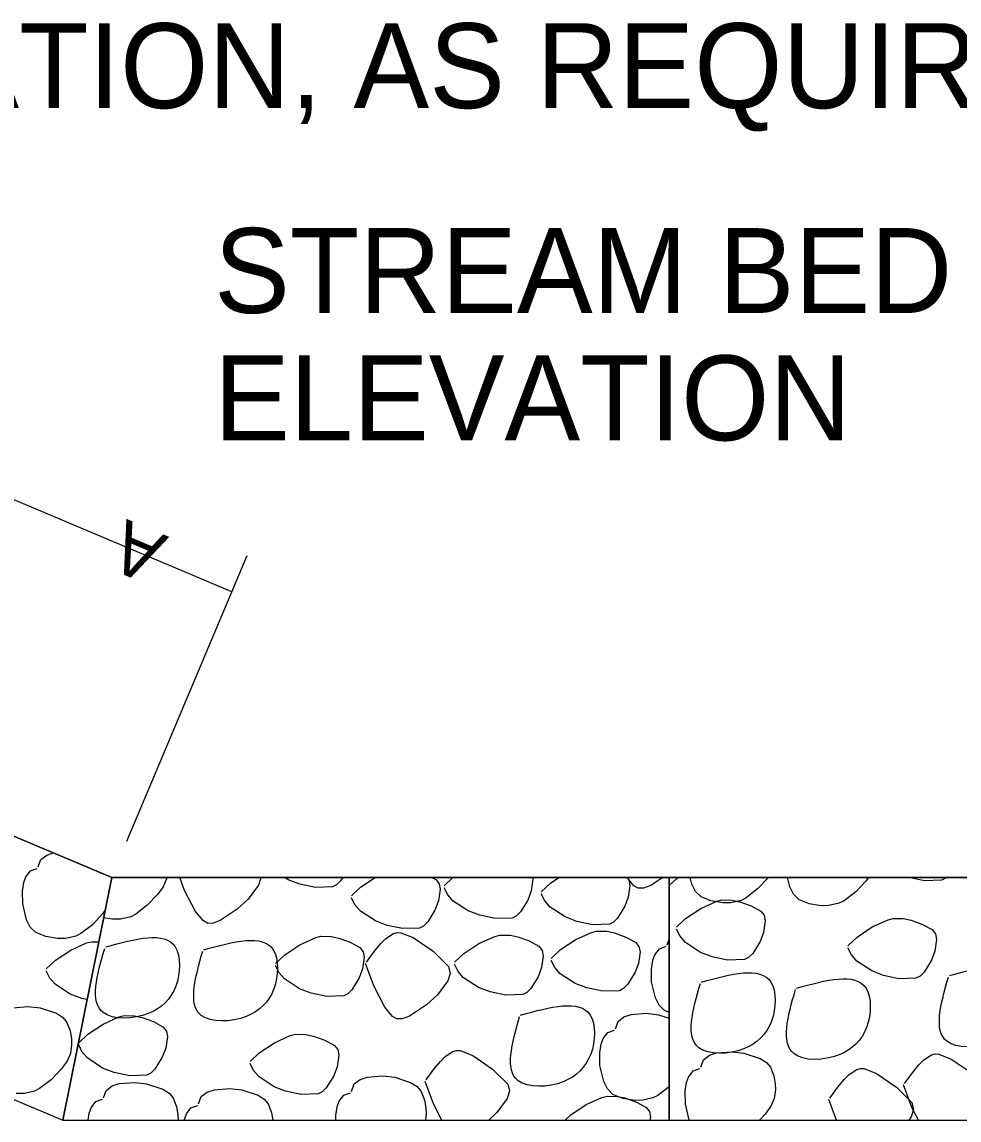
# Model space of a CAD drawing. Extents: x 3 to 3592, y -602 to 1171.
# Drawn here: x 2823.27 to 2861.89, y -276.9 to -231.64 of the extents above; entities that cross this region are included whole.
import ezdxf

# ---------------------------------------------------------------- set-up
doc = ezdxf.new("R2010")
doc.units = 0
doc.layers.add('2', color=7, linetype='Continuous')
doc.layers.add('3', color=7, linetype='Continuous')

msp = doc.modelspace()

# ---------------------------------------------------------------- linework, layer by layer
at = {"layer": '2'}
for p, q in [((2831.922, -255.129), (2816.821, -248.771)), ((2827.596, -265.403), (2832.553, -253.631)), ((2826.966, -266.901), (2824.946, -276.901)), ((2849.946, -276.901), (2849.946, -266.901))]:
    msp.add_line(p, q, dxfattribs=at)
for points in [[(2764.046, -240.408), (2826.966, -266.901), (2872.927, -266.901), (2935.846, -240.408)], [(2777.446, -256.901), (2824.946, -276.901), (2874.946, -276.901), (2922.446, -256.901)], [(2824.046, -266.166), (2824.288, -265.984)], [(2824.288, -265.984), (2824.566, -265.89)], [(2823.619, -266.629), (2823.896, -266.531)], [(2823.936, -266.471), (2824.046, -266.166)], [(2823.346, -267.108), (2823.429, -266.879)], [(2823.429, -266.879), (2823.619, -266.629)], [(2826.956, -266.897), (2826.961, -266.924)], [(2829.227, -266.966), (2829.09, -267.284)], [(2829.237, -266.901), (2829.227, -266.966)], [(2829.973, -267.436), (2829.775, -266.901)], [(2833.117, -266.919), (2833.021, -267.221)], [(2833.113, -266.901), (2833.117, -266.919)], [(2834.246, -266.996), (2834.1, -266.901)], [(2834.724, -267.179), (2834.246, -266.996)], [(2836.487, -266.901), (2836.4, -267.041)], [(2837.225, -267.298), (2837.824, -266.901)], [(2840.156, -266.901), (2840.323, -266.991)], [(2840.323, -266.991), (2840.463, -267.168)], [(2840.673, -267.244), (2841.031, -266.901)], [(2844.33, -266.978), (2844.26, -267.458)], [(2844.315, -266.901), (2844.33, -266.978)], [(2845.049, -267.135), (2845.403, -266.901)], [(2848.204, -266.901), (2848.287, -267.006)], [(2848.496, -267.243), (2848.213, -266.901)], [(2848.287, -267.006), (2848.33, -267.229)], [(2849.69, -266.901), (2849.191, -267.229)], [(2850.235, -266.969), (2849.946, -267.235)], [(2850.286, -266.901), (2850.235, -266.969)], [(2850.878, -267.177), (2850.813, -266.901)], [(2854.011, -266.934), (2853.592, -267.375)], [(2854.036, -266.901), (2854.011, -266.934)], [(2854.92, -267.295), (2854.828, -266.901)], [(2858.164, -266.901), (2858.053, -267.052)], [(2859.829, -266.902), (2859.825, -266.901)], [(2860.47, -267.037), (2859.829, -266.902)], [(2861.337, -266.929), (2861.171, -267.016)], [(2861.366, -266.901), (2861.337, -266.929)], [(2823.289, -267.466), (2823.346, -267.108)], [(2829.09, -267.284), (2828.854, -267.607)], [(2830.427, -268.304), (2829.973, -267.436)], [(2833.021, -267.221), (2832.593, -267.8)], [(2835.365, -267.314), (2834.724, -267.179)], [(2836.066, -267.293), (2835.365, -267.314)], [(2836.232, -267.206), (2836.066, -267.293)], [(2836.4, -267.041), (2836.232, -267.206)], [(2836.849, -267.657), (2837.225, -267.298)], [(2840.506, -267.392), (2840.437, -267.872)], [(2840.463, -267.168), (2840.506, -267.392)], [(2840.818, -267.619), (2840.673, -267.325)], [(2844.26, -267.458), (2844.117, -267.837)], [(2844.673, -267.495), (2845.049, -267.135)], [(2848.33, -267.229), (2848.261, -267.709)], [(2848.673, -267.348), (2848.496, -267.243)], [(2848.893, -267.342), (2848.673, -267.348)], [(2849.191, -267.229), (2848.893, -267.342)], [(2851.031, -267.478), (2850.878, -267.177)], [(2853.592, -267.375), (2853.116, -267.742)], [(2855.073, -267.596), (2854.92, -267.295)], [(2858.053, -267.052), (2857.634, -267.493)], [(2861.171, -267.016), (2860.47, -267.037)], [(2823.299, -267.989), (2823.289, -267.466)], [(2828.854, -267.607), (2828.435, -268.048)], [(2832.593, -267.8), (2832.144, -268.213)], [(2836.995, -268.032), (2836.849, -267.738)], [(2840.437, -267.872), (2840.293, -268.251)], [(2841.043, -267.877), (2840.818, -267.619)], [(2841.659, -268.28), (2841.043, -267.877)], [(2844.117, -267.837), (2843.814, -268.325)], [(2844.819, -267.87), (2844.673, -267.576)], [(2845.044, -268.128), (2844.819, -267.87)], [(2848.261, -267.709), (2848.118, -268.088)], [(2851.258, -267.702), (2851.031, -267.478)], [(2851.254, -268.176), (2851.904, -267.882)], [(2851.669, -267.868), (2851.258, -267.702)], [(2852.157, -267.949), (2851.669, -267.868)], [(2851.904, -267.882), (2852.118, -267.829)], [(2852.118, -267.829), (2852.533, -267.833)], [(2852.909, -267.848), (2852.491, -267.943)], [(2852.533, -267.833), (2852.859, -267.901)], [(2852.859, -267.901), (2853.328, -268.072)], [(2853.116, -267.742), (2852.909, -267.848)], [(2855.3, -267.82), (2855.073, -267.596)], [(2855.711, -267.986), (2855.3, -267.82)], [(2857.158, -267.86), (2856.951, -267.966)], [(2857.634, -267.493), (2857.158, -267.86)], [(2823.454, -268.652), (2823.299, -267.989)], [(2826.689, -268.271), (2826.587, -268.409)], [(2828.435, -268.048), (2827.959, -268.415)], [(2830.746, -268.69), (2830.427, -268.304)], [(2832.144, -268.213), (2831.441, -268.676)], [(2837.22, -268.29), (2836.995, -268.032)], [(2837.836, -268.694), (2837.22, -268.29)], [(2840.293, -268.251), (2839.991, -268.738)], [(2842.138, -268.463), (2841.659, -268.28)], [(2843.814, -268.325), (2843.646, -268.49)], [(2845.66, -268.531), (2845.044, -268.128)], [(2848.118, -268.088), (2847.815, -268.576)], [(2850.624, -268.593), (2851.254, -268.176)], [(2852.491, -267.943), (2852.157, -267.949)], [(2853.328, -268.072), (2853.722, -268.286)], [(2853.722, -268.286), (2853.862, -268.463)], [(2856.198, -268.067), (2855.711, -267.986)], [(2856.533, -268.061), (2856.198, -268.067)], [(2856.951, -267.966), (2856.533, -268.061)], [(2823.608, -268.953), (2823.454, -268.652)], [(2826.587, -268.409), (2826.169, -268.85)], [(2826.999, -268.621), (2826.631, -268.561)], [(2827.334, -268.616), (2826.999, -268.621)], [(2827.752, -268.52), (2827.334, -268.616)], [(2827.959, -268.415), (2827.752, -268.52)], [(2830.923, -268.795), (2830.746, -268.69)], [(2831.143, -268.789), (2830.923, -268.795)], [(2831.441, -268.676), (2831.143, -268.789)], [(2838.315, -268.877), (2837.836, -268.694)], [(2839.991, -268.738), (2839.822, -268.904)], [(2842.779, -268.598), (2842.138, -268.463)], [(2843.48, -268.577), (2842.779, -268.598)], [(2843.646, -268.49), (2843.48, -268.577)], [(2846.139, -268.714), (2845.66, -268.531)], [(2846.779, -268.849), (2846.139, -268.714)], [(2847.646, -268.741), (2847.481, -268.828)], [(2847.815, -268.576), (2847.646, -268.741)], [(2850.248, -268.952), (2850.624, -268.593)], [(2853.905, -268.687), (2853.836, -269.167)], [(2853.862, -268.463), (2853.905, -268.687)], [(2858.319, -268.943), (2858.969, -268.65)], [(2858.969, -268.65), (2859.183, -268.597)], [(2859.183, -268.597), (2859.598, -268.601)], [(2859.598, -268.601), (2859.924, -268.668)], [(2859.924, -268.668), (2860.393, -268.84)], [(2823.835, -269.177), (2823.608, -268.953)], [(2824.246, -269.343), (2823.835, -269.177)], [(2825.693, -269.217), (2825.485, -269.323)], [(2826.169, -268.85), (2825.693, -269.217)], [(2838.266, -269.423), (2838.577, -269.216)], [(2838.955, -269.012), (2838.315, -268.877)], [(2838.577, -269.216), (2838.732, -269.172)], [(2838.732, -269.172), (2838.885, -269.179)], [(2838.885, -269.179), (2839.395, -269.384)], [(2839.656, -268.99), (2838.955, -269.012)], [(2839.822, -268.904), (2839.656, -268.99)], [(2846.092, -269.461), (2846.743, -269.167)], [(2846.743, -269.167), (2846.956, -269.114)], [(2847.481, -268.828), (2846.779, -268.849)], [(2846.956, -269.114), (2847.372, -269.119)], [(2847.372, -269.119), (2847.697, -269.186)], [(2847.697, -269.186), (2848.166, -269.357)], [(2850.394, -269.327), (2850.248, -269.033)], [(2853.836, -269.167), (2853.693, -269.546)], [(2857.689, -269.36), (2858.319, -268.943)], [(2860.393, -268.84), (2860.787, -269.054)], [(2860.787, -269.054), (2860.927, -269.231)], [(2860.927, -269.231), (2860.97, -269.455)], [(2824.733, -269.424), (2824.246, -269.343)], [(2825.068, -269.418), (2824.733, -269.424)], [(2825.485, -269.323), (2825.068, -269.418)], [(2825.275, -269.897), (2825.926, -269.604)], [(2825.926, -269.604), (2826.139, -269.551)], [(2826.139, -269.551), (2826.43, -269.553)], [(2834.098, -270.093), (2834.727, -269.676)], [(2834.727, -269.676), (2835.378, -269.382)], [(2835.378, -269.382), (2835.591, -269.329)], [(2835.591, -269.329), (2836.007, -269.333)], [(2836.007, -269.333), (2836.332, -269.401)], [(2836.332, -269.401), (2836.802, -269.572)], [(2836.802, -269.572), (2837.196, -269.786)], [(2837.797, -269.947), (2838.061, -269.627)], [(2838.061, -269.627), (2838.266, -269.423)], [(2839.395, -269.384), (2840.212, -269.944)], [(2841.477, -270.041), (2842.106, -269.624)], [(2842.106, -269.624), (2842.757, -269.33)], [(2842.757, -269.33), (2842.97, -269.277)], [(2842.97, -269.277), (2843.386, -269.281)], [(2843.386, -269.281), (2843.711, -269.349)], [(2843.711, -269.349), (2844.18, -269.52)], [(2844.18, -269.52), (2844.575, -269.734)], [(2845.463, -269.878), (2846.092, -269.461)], [(2848.166, -269.357), (2848.561, -269.571)], [(2848.561, -269.571), (2848.701, -269.749)], [(2849.861, -269.681), (2849.946, -269.444)], [(2850.619, -269.585), (2850.394, -269.327)], [(2851.235, -269.989), (2850.619, -269.585)], [(2853.693, -269.546), (2853.39, -270.033)], [(2857.313, -269.72), (2857.689, -269.36)], [(2860.97, -269.455), (2860.901, -269.935)], [(2824.646, -270.314), (2825.275, -269.897)], [(2833.722, -270.452), (2834.098, -270.093)], [(2837.196, -269.786), (2837.336, -269.963)], [(2837.336, -269.963), (2837.379, -270.187)], [(2837.471, -270.391), (2837.797, -269.947)], [(2840.212, -269.944), (2840.844, -270.573)], [(2841.101, -270.4), (2841.477, -270.041)], [(2844.575, -269.734), (2844.715, -269.911)], [(2844.758, -270.135), (2844.689, -270.615)], [(2844.715, -269.911), (2844.758, -270.135)], [(2845.087, -270.238), (2845.463, -269.878)], [(2848.744, -269.972), (2848.675, -270.452)], [(2848.701, -269.749), (2848.744, -269.972)], [(2849.271, -270.318), (2849.353, -270.089)], [(2849.353, -270.089), (2849.544, -269.839)], [(2849.544, -269.839), (2849.82, -269.741)], [(2851.714, -270.172), (2851.235, -269.989)], [(2852.354, -270.307), (2851.714, -270.172)], [(2853.39, -270.033), (2853.221, -270.199)], [(2857.459, -270.095), (2857.313, -269.801)], [(2857.684, -270.353), (2857.459, -270.095)], [(2860.901, -269.935), (2860.758, -270.314)], [(2824.27, -270.674), (2824.646, -270.314)], [(2833.868, -270.827), (2833.722, -270.533)], [(2837.379, -270.187), (2837.31, -270.667)], [(2837.773, -271.374), (2837.431, -270.451)], [(2840.844, -270.573), (2840.917, -270.858)], [(2841.247, -270.775), (2841.101, -270.481)], [(2844.689, -270.615), (2844.545, -270.994)], [(2845.233, -270.613), (2845.087, -270.319)], [(2845.457, -270.871), (2845.233, -270.613)], [(2848.675, -270.452), (2848.531, -270.831)], [(2849.213, -270.676), (2849.271, -270.318)], [(2853.055, -270.285), (2852.354, -270.307)], [(2853.221, -270.199), (2853.055, -270.285)], [(2858.3, -270.756), (2857.684, -270.353)], [(2860.758, -270.314), (2860.455, -270.801)], [(2824.416, -271.049), (2824.27, -270.755)], [(2824.64, -271.307), (2824.416, -271.049)], [(2834.092, -271.085), (2833.868, -270.827)], [(2837.166, -271.046), (2836.864, -271.533)], [(2837.31, -270.667), (2837.166, -271.046)], [(2840.917, -270.858), (2840.821, -271.16)], [(2841.471, -271.033), (2841.247, -270.775)], [(2842.088, -271.437), (2841.471, -271.033)], [(2844.545, -270.994), (2844.242, -271.481)], [(2846.074, -271.274), (2845.457, -270.871)], [(2848.531, -270.831), (2848.228, -271.319)], [(2849.224, -271.2), (2849.213, -270.676)], [(2858.779, -270.94), (2858.3, -270.756)], [(2859.419, -271.075), (2858.779, -270.94)], [(2860.12, -271.053), (2859.419, -271.075)], [(2860.286, -270.966), (2860.12, -271.053)], [(2860.455, -270.801), (2860.286, -270.966)], [(2825.257, -271.71), (2824.64, -271.307)], [(2834.709, -271.489), (2834.092, -271.085)], [(2835.188, -271.672), (2834.709, -271.489)], [(2836.864, -271.533), (2836.695, -271.699)], [(2838.227, -272.243), (2837.773, -271.374)], [(2840.821, -271.16), (2840.393, -271.739)], [(2842.566, -271.62), (2842.088, -271.437)], [(2844.242, -271.481), (2844.074, -271.647)], [(2846.552, -271.457), (2846.074, -271.274)], [(2847.193, -271.592), (2846.552, -271.457)], [(2848.06, -271.484), (2847.894, -271.571)], [(2848.228, -271.319), (2848.06, -271.484)], [(2849.379, -271.862), (2849.224, -271.2)], [(2825.736, -271.894), (2825.257, -271.71)], [(2825.948, -271.938), (2825.736, -271.894)], [(2835.828, -271.807), (2835.188, -271.672)], [(2836.529, -271.785), (2835.828, -271.807)], [(2836.695, -271.699), (2836.529, -271.785)], [(2840.393, -271.739), (2839.944, -272.152)], [(2843.207, -271.755), (2842.566, -271.62)], [(2843.908, -271.733), (2843.207, -271.755)], [(2844.074, -271.647), (2843.908, -271.733)], [(2847.894, -271.571), (2847.193, -271.592)], [(2849.532, -272.163), (2849.379, -271.862)], [(2822.885, -272.274), (2823.513, -272.224)], [(2823.513, -272.224), (2824.015, -272.282)], [(2824.015, -272.282), (2824.687, -272.502)], [(2838.546, -272.628), (2838.227, -272.243)], [(2839.944, -272.152), (2839.241, -272.614)], [(2849.76, -272.387), (2849.532, -272.163)], [(2849.946, -272.462), (2849.76, -272.387)], [(2824.687, -272.502), (2824.94, -272.666)], [(2824.94, -272.666), (2825.106, -272.86)], [(2825.106, -272.86), (2825.248, -273.225)], [(2826.612, -272.945), (2827.262, -272.651)], [(2827.262, -272.651), (2827.476, -272.598)], [(2827.476, -272.598), (2827.891, -272.602)], [(2827.891, -272.602), (2828.217, -272.67)], [(2828.217, -272.67), (2828.686, -272.841)], [(2828.686, -272.841), (2829.08, -273.055)], [(2838.723, -272.734), (2838.546, -272.628)], [(2838.943, -272.728), (2838.723, -272.734)], [(2839.241, -272.614), (2838.943, -272.728)], [(2847.728, -273.138), (2847.838, -272.833)], [(2847.838, -272.833), (2848.08, -272.651)], [(2848.08, -272.651), (2848.375, -272.552)], [(2848.375, -272.552), (2849.003, -272.502)], [(2849.003, -272.502), (2849.504, -272.56)], [(2849.504, -272.56), (2849.946, -272.705)], [(2825.248, -273.225), (2825.305, -273.546)], [(2825.982, -273.362), (2826.612, -272.945)], [(2829.08, -273.055), (2829.221, -273.233)], [(2829.221, -273.233), (2829.264, -273.456)], [(2847.221, -273.546), (2847.411, -273.296)], [(2847.411, -273.296), (2847.688, -273.199)], [(2825.313, -273.795), (2825.263, -274.158)], [(2825.305, -273.546), (2825.313, -273.795)], [(2825.606, -273.722), (2825.982, -273.362)], [(2829.264, -273.456), (2829.194, -273.936)], [(2833.047, -274.13), (2833.677, -273.713)], [(2833.677, -273.713), (2834.327, -273.419)], [(2834.327, -273.419), (2834.541, -273.366)], [(2834.541, -273.366), (2834.956, -273.37)], [(2834.956, -273.37), (2835.282, -273.438)], [(2835.282, -273.438), (2835.751, -273.609)], [(2835.751, -273.609), (2836.145, -273.823)], [(2847.081, -274.134), (2847.138, -273.775)], [(2847.138, -273.775), (2847.221, -273.546)], [(2825.263, -274.158), (2825.126, -274.476)], [(2825.752, -274.097), (2825.606, -273.803)], [(2825.977, -274.354), (2825.752, -274.097)], [(2829.194, -273.936), (2829.051, -274.315)], [(2832.671, -274.49), (2833.047, -274.13)], [(2836.145, -273.823), (2836.286, -274)], [(2836.329, -274.224), (2836.259, -274.704)], [(2836.286, -274), (2836.329, -274.224)], [(2840.718, -274.278), (2841.029, -274.071)], [(2841.029, -274.071), (2841.184, -274.028)], [(2841.184, -274.028), (2841.337, -274.035)], [(2841.337, -274.035), (2841.848, -274.239)], [(2841.848, -274.239), (2842.664, -274.799)], [(2847.091, -274.657), (2847.081, -274.134)], [(2851.363, -274.414), (2851.605, -274.232)], [(2851.605, -274.232), (2851.899, -274.132)], [(2851.899, -274.132), (2852.528, -274.083)], [(2852.528, -274.083), (2853.029, -274.141)], [(2853.029, -274.141), (2853.702, -274.361)], [(2860.442, -274.426), (2860.753, -274.219)], [(2860.753, -274.219), (2860.908, -274.176)], [(2860.908, -274.176), (2861.061, -274.183)], [(2861.061, -274.183), (2861.572, -274.387)], [(2825.126, -274.476), (2824.89, -274.799)], [(2826.593, -274.758), (2825.977, -274.354)], [(2829.051, -274.315), (2828.748, -274.803)], [(2832.817, -274.864), (2832.671, -274.57)], [(2836.259, -274.704), (2836.116, -275.083)], [(2840.249, -274.802), (2840.513, -274.483)], [(2840.513, -274.483), (2840.718, -274.278)], [(2847.246, -275.319), (2847.091, -274.657)], [(2851.253, -274.719), (2851.363, -274.414)], [(2853.702, -274.361), (2853.954, -274.525)], [(2853.954, -274.525), (2854.12, -274.719)], [(2859.973, -274.95), (2860.237, -274.631)], [(2860.237, -274.631), (2860.442, -274.426)], [(2861.572, -274.387), (2862.389, -274.947)], [(2824.89, -274.799), (2824.471, -275.239)], [(2827.072, -274.941), (2826.593, -274.758)], [(2827.713, -275.076), (2827.072, -274.941)], [(2828.414, -275.055), (2827.713, -275.076)], [(2828.58, -274.968), (2828.414, -275.055)], [(2828.748, -274.803), (2828.58, -274.968)], [(2833.042, -275.122), (2832.817, -274.864)], [(2833.658, -275.526), (2833.042, -275.122)], [(2836.116, -275.083), (2835.813, -275.57)], [(2837.207, -275.232), (2837.501, -275.132)], [(2837.501, -275.132), (2838.129, -275.083)], [(2838.129, -275.083), (2838.631, -275.14)], [(2838.631, -275.14), (2839.304, -275.361)], [(2839.923, -275.246), (2840.249, -274.802)], [(2842.664, -274.799), (2843.296, -275.428)], [(2850.663, -275.356), (2850.745, -275.127)], [(2850.745, -275.127), (2850.936, -274.877)], [(2850.936, -274.877), (2851.212, -274.78)], [(2854.12, -274.719), (2854.262, -275.084)], [(2854.262, -275.084), (2854.319, -275.405)], [(2857.164, -275.23), (2857.369, -275.026)], [(2857.369, -275.026), (2857.68, -274.819)], [(2857.68, -274.819), (2857.835, -274.775)], [(2857.835, -274.775), (2857.988, -274.782)], [(2857.988, -274.782), (2858.499, -274.987)], [(2858.499, -274.987), (2859.315, -275.547)], [(2859.647, -275.394), (2859.973, -274.95)], [(2823.995, -275.607), (2823.788, -275.712)], [(2824.471, -275.239), (2823.995, -275.607)], [(2826.74, -275.68), (2826.983, -275.497)], [(2826.983, -275.497), (2827.277, -275.398)], [(2827.277, -275.398), (2827.905, -275.348)], [(2827.905, -275.348), (2828.407, -275.406)], [(2828.407, -275.406), (2829.08, -275.627)], [(2831.198, -275.649), (2831.826, -275.599)], [(2831.826, -275.599), (2832.327, -275.657)], [(2834.137, -275.709), (2833.658, -275.526)], [(2835.813, -275.57), (2835.645, -275.736)], [(2836.855, -275.719), (2836.965, -275.414)], [(2836.965, -275.414), (2837.207, -275.232)], [(2839.304, -275.361), (2839.556, -275.524)], [(2839.556, -275.524), (2839.722, -275.719)], [(2840.226, -276.23), (2839.883, -275.307)], [(2843.296, -275.428), (2843.37, -275.713)], [(2847.4, -275.62), (2847.246, -275.319)], [(2849.946, -275.528), (2849.485, -275.885)], [(2850.605, -275.714), (2850.663, -275.356)], [(2854.319, -275.405), (2854.328, -275.654)], [(2856.574, -275.994), (2856.9, -275.55)], [(2856.9, -275.55), (2857.164, -275.23)], [(2859.315, -275.547), (2859.947, -276.176)], [(2859.95, -276.378), (2859.607, -275.455)], [(2823.37, -275.807), (2823.035, -275.813)], [(2823.788, -275.712), (2823.37, -275.807)], [(2826.314, -276.143), (2826.59, -276.045)], [(2826.63, -275.985), (2826.74, -275.68)], [(2829.08, -275.627), (2829.332, -275.79)], [(2829.332, -275.79), (2829.498, -275.985)], [(2829.498, -275.985), (2829.64, -276.35)], [(2830.551, -276.236), (2830.661, -275.931)], [(2830.661, -275.931), (2830.903, -275.748)], [(2830.903, -275.748), (2831.198, -275.649)], [(2832.327, -275.657), (2833, -275.878)], [(2833, -275.878), (2833.252, -276.041)], [(2833.252, -276.041), (2833.419, -276.236)], [(2834.778, -275.844), (2834.137, -275.709)], [(2835.479, -275.823), (2834.778, -275.844)], [(2835.645, -275.736), (2835.479, -275.823)], [(2836.347, -276.126), (2836.538, -275.877)], [(2836.538, -275.877), (2836.814, -275.779)], [(2839.722, -275.719), (2839.864, -276.084)], [(2843.274, -276.015), (2842.846, -276.594)], [(2843.37, -275.713), (2843.274, -276.015)], [(2846.52, -276.266), (2847.171, -275.973)], [(2847.171, -275.973), (2847.384, -275.92)], [(2847.384, -275.92), (2847.8, -275.924)], [(2847.627, -275.845), (2847.4, -275.62)], [(2848.038, -276.011), (2847.627, -275.845)], [(2847.8, -275.924), (2848.125, -275.991)], [(2848.525, -276.091), (2848.038, -276.011)], [(2848.125, -275.991), (2848.594, -276.163)], [(2849.277, -275.99), (2848.86, -276.085)], [(2849.485, -275.885), (2849.277, -275.99)], [(2850.616, -276.238), (2850.605, -275.714)], [(2854.278, -276.017), (2854.141, -276.335)], [(2854.328, -275.654), (2854.278, -276.017)], [(2856.848, -276.901), (2856.534, -276.055)], [(2826.041, -276.621), (2826.123, -276.392)], [(2826.123, -276.392), (2826.314, -276.143)], [(2829.64, -276.35), (2829.697, -276.67)], [(2830.044, -276.643), (2830.234, -276.394)], [(2830.234, -276.394), (2830.51, -276.296)], [(2833.419, -276.236), (2833.56, -276.601)], [(2836.207, -276.714), (2836.265, -276.356)], [(2836.265, -276.356), (2836.347, -276.126)], [(2839.864, -276.084), (2839.921, -276.404)], [(2839.921, -276.404), (2839.93, -276.654)], [(2840.576, -276.901), (2840.226, -276.23)], [(2845.891, -276.683), (2846.52, -276.266)], [(2848.86, -276.085), (2848.525, -276.091)], [(2848.594, -276.163), (2848.989, -276.377)], [(2848.989, -276.377), (2849.129, -276.554)], [(2850.771, -276.9), (2850.616, -276.238)], [(2854.141, -276.335), (2853.904, -276.658)], [(2860.021, -276.461), (2859.925, -276.763)], [(2859.947, -276.176), (2860.021, -276.461)], [(2860.223, -276.901), (2859.95, -276.378)], [(2825.996, -276.901), (2826.041, -276.621)], [(2829.697, -276.67), (2829.705, -276.901)], [(2829.957, -276.901), (2829.961, -276.872)], [(2829.961, -276.872), (2830.044, -276.643)], [(2833.56, -276.601), (2833.614, -276.901)], [(2836.211, -276.901), (2836.207, -276.714)], [(2839.93, -276.654), (2839.895, -276.901)], [(2842.846, -276.594), (2842.512, -276.901)], [(2845.664, -276.901), (2845.891, -276.683)], [(2849.129, -276.554), (2849.172, -276.778)], [(2849.172, -276.778), (2849.154, -276.901)], [(2850.772, -276.901), (2850.771, -276.9)], [(2853.904, -276.658), (2853.673, -276.901)], [(2859.925, -276.763), (2859.823, -276.901)]]:
    msp.add_lwpolyline(points, dxfattribs=at)
for points in [[(2826.966, -266.901), (2805.077, -257.684), (2801.196, -266.901), (2824.946, -276.901)], [(2849.946, -266.901), (2826.966, -266.901), (2824.946, -276.901), (2849.946, -276.901)], [(2872.927, -266.901), (2849.946, -266.901), (2849.946, -276.901), (2874.946, -276.901)]]:
    msp.add_lwpolyline(points, close=True, dxfattribs=at)
for points in [[(2826.718, -269.765), (2829.585, -269.765), (2829.606, -271.381), (2828.475, -272.512), (2826.617, -272.471), (2826.677, -269.826)], [(2830.759, -269.883), (2833.627, -269.883), (2833.647, -271.499), (2832.516, -272.63), (2830.658, -272.589), (2830.719, -269.944)], [(2851.272, -271.215), (2854.14, -271.215), (2854.16, -272.831), (2853.029, -273.962), (2851.171, -273.921), (2851.232, -271.276)], [(2861.496, -270.949), (2864.364, -270.949), (2864.384, -272.565), (2863.253, -273.696), (2861.395, -273.656), (2861.456, -271.01)], [(2855.193, -271.466), (2858.06, -271.466), (2858.081, -273.082), (2856.95, -274.213), (2855.092, -274.172), (2855.152, -271.527)], [(2843.823, -272.574), (2846.69, -272.574), (2846.711, -274.19), (2845.58, -275.321), (2843.722, -275.281), (2843.782, -272.635)]]:
    msp.add_spline(points, degree=3, dxfattribs=at)

# ---------------------------------------------------------------- texts
msp.add_text('A', height=2.166, rotation=157.1665, dxfattribs=at).set_placement((2829.347, -252.869))
at = {"layer": '3'}
for s, p in [('FLOW ELEVATION, AS REQUIRED.', (2793.242, -235.197)), ('STREAM BED', (2831.188, -243.638)), ('ELEVATION', (2831.188, -248.888))]:
    msp.add_text(s, height=3.5, dxfattribs=at).set_placement(p)

doc.saveas('drawing.dxf')
